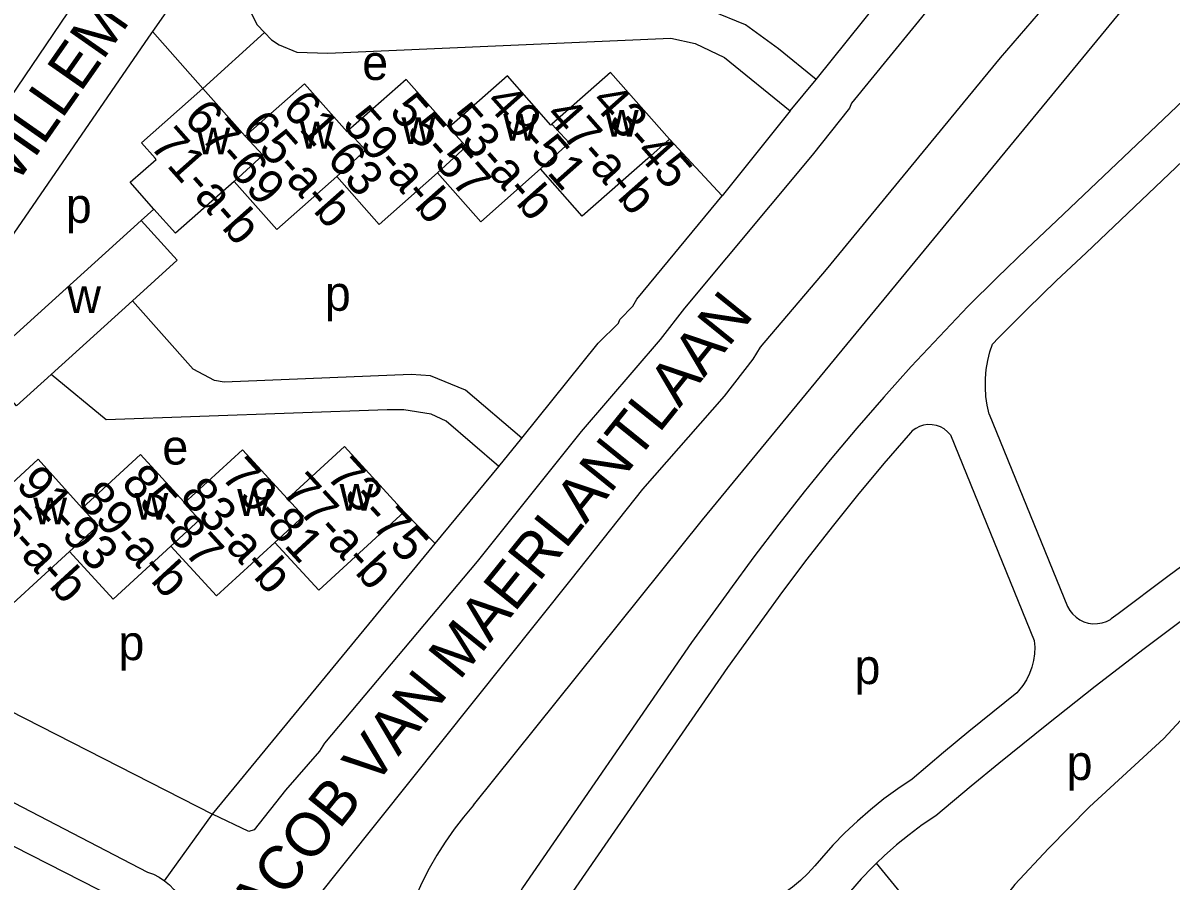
# Model space of a CAD drawing. Extents: x 159700 to 161346, y 381730 to 382922.
# Drawn here: x 160840.3 to 160971.8, y 381917.2 to 382015.5 of the extents above; entities that cross this region are included whole.
import ezdxf

# ---------------------------------------------------------------- set-up
doc = ezdxf.new("R2010")
doc.units = 0
for name, color, linetype in [('BLT_Basislijn', 7, 'Continuous'), ('BLT_Bebouwing', 7, 'Continuous'), ('BLT_Centroide', 7, 'Continuous'), ('BLT_Huisnummer_reeks', 7, 'Continuous'), ('BLT_Onderverdeling_panden', 7, 'Continuous'), ('BLT_Straatnaam', 7, 'Continuous'), ('BLT_Vlakafsluiter', 7, 'Continuous')]:
    doc.layers.add(name, color=color, linetype=linetype)

msp = doc.modelspace()

# ---------------------------------------------------------------- linework, layer by layer
at = {"layer": 'BLT_Basislijn'}
for p, q in [((160958.66, 381992.87), (160992.04, 382024.66)), ((160918.1, 381958.62), (160970.62, 382022.44)), ((160855.12, 382014.54), (160860.87, 382007.99)), ((160867.92, 382014.43), (160860.87, 382007.99)), ((160928.14, 382005.45), (160931.13, 382009.02)), ((160928.14, 382005.45), (160920.36, 381995.73)), ((160962.05, 381989.2), (160978.76, 382005.11)), ((160920.36, 381995.73), (160914.31, 382002.2)), ((160705.83, 381995.32), (160854.54, 381918.26)), ((160853.8, 381992.9), (160855.27, 381994.19)), ((160950.93, 381970.71), (160959.9, 381948.7)), ((160894.76, 381964.73), (160897.42, 381967.95)), ((160946.49, 381968.34), (160956.09, 381944.8)), ((160887.46, 381955.88), (160894.76, 381964.73)), ((160887.46, 381955.88), (160883.94, 381959.54)), ((160891.86, 381925.93), (160918.1, 381958.62)), ((160921.1, 381950.42), (160916.85, 381944.54)), ((160925.16, 381947.5), (160920.96, 381941.7)), ((160945.68, 381931.96), (160942.1, 381928.92)), ((160948.87, 381928.11), (160944.81, 381924.72)), ((160854.63, 381913.36), (160834.95, 381923.34))]:
    msp.add_line(p, q, dxfattribs=at)
for points in [[(160869.82, 381910.13), (160903.05, 381951.79), (160911.26, 381962.12), (160920.61, 381972.78), (160923.88, 381976.99), (160924.72, 381978.39), (160932.29, 381987.27), (160952.21, 382011.52), (160956.58, 382016.57), (160959.68, 382020.5), (160961.97, 382022.98), (160980.7, 382045.61), (160986.69, 382052.53), (161016.71, 382083.47)], [(160883.99, 382072.81), (160870.54, 382052.66), (160865.04, 382045.05), (160858.65, 382035.7), (160858.47, 382035.66), (160858.03, 382034.8), (160853.13, 382028.14), (160852.91, 382027.61), (160852.73, 382027.57), (160828.11, 381991.25), (160827.9, 381991.18), (160827.79, 381990.75), (160827.27, 381990.23), (160823.65, 381984.68), (160823.44, 381984.61), (160821.73, 381981.82), (160817.59, 381976.14), (160816.77, 381975.28), (160804.69, 381957.09), (160803.57, 381956.03), (160800.6, 381955.73), (160797.89, 381956.96), (160781.74, 381965.52)], [(160884, 382056.53), (160883.61, 382055.97), (160866.64, 382031.03), (160855.12, 382014.54)], [(160931.13, 382009.02), (160947.17, 382029.06), (160956.82, 382040.05), (160957.75, 382041.22), (160958.14, 382041.7)], [(160931.13, 382009.02), (160926.81, 382012.53), (160923, 382015.29), (160919.1, 382016.89), (160916.05, 382017.84), (160909.67, 382018.24), (160883.9, 382017.28), (160882.67, 382017.87), (160881.77, 382018.95), (160880.98, 382021.61), (160879.95, 382023.99), (160878.1, 382026.03), (160875.48, 382027.17), (160874.43, 382027.33), (160871.72, 382027.17), (160869.11, 382026.16), (160867.36, 382024.66), (160866.35, 382022.4), (160865.9, 382020.6), (160866.09, 382017.23), (160867.1, 382015.29), (160867.92, 382014.43)], [(160946.57, 382020.33), (160935.16, 382006.34), (160934.94, 382005.76), (160930.65, 382000.36), (160916.04, 381982.84), (160913.24, 381979.24), (160904.18, 381968.73), (160892.29, 381953.83), (160874.79, 381933.03), (160874.24, 381932.11), (160870.34, 381927.64), (160866.74, 381923.09), (160866.14, 381922.9), (160861.98, 381924.9)], [(160855.12, 382014.54), (160854.65, 382013.88), (160825.11, 381970.95)], [(160867.92, 382014.43), (160868.74, 382013.58), (160869.6, 382013), (160871.62, 382012.18), (160875.2, 382012.05), (160914.45, 382013.77), (160917.26, 382013.14), (160920.6, 382011.55), (160928.14, 382005.45)], [(160897.42, 381967.95), (160906.16, 381978.82), (160908.48, 381981.13), (160908.64, 381981.55), (160910.1, 381983.08), (160910.58, 381983.88), (160919.81, 381995.05), (160920.36, 381995.73)], [(160958.66, 381992.87), (160955.22, 381989.65), (160951.83, 381986.36), (160948.5, 381983.02), (160945.23, 381979.62), (160942.01, 381976.17), (160938.85, 381972.67), (160935.75, 381969.11), (160932.72, 381965.49), (160929.74, 381961.83), (160926.83, 381958.12), (160923.98, 381954.36), (160921.2, 381950.55), (160921.1, 381950.42)], [(160962.05, 381989.2), (160958.64, 381986), (160955.28, 381982.74), (160951.98, 381979.43), (160951.31, 381978.74)], [(160897.42, 381967.95), (160890.95, 381973.45), (160886.96, 381975.1), (160884.73, 381975.26), (160863.33, 381974.39), (160862.22, 381974.55), (160859.76, 381975.87), (160852.81, 381983.68)], [(160950.93, 381970.71), (160950.7, 381971.72), (160950.55, 381972.74), (160950.49, 381973.77), (160950.5, 381974.8), (160950.59, 381975.83), (160950.76, 381976.85), (160951.01, 381977.85), (160951.31, 381978.74)], [(160894.76, 381964.73), (160888.72, 381969.91), (160887.03, 381970.72), (160883.9, 381971.2), (160881.99, 381971.2), (160849.78, 381970.05), (160843.48, 381975.24)], [(160825.11, 381970.95), (160824.58, 381970.18), (160819.71, 381963.29), (160813.49, 381953.61), (160813.55, 381950.74), (160814.22, 381949.34), (160815.59, 381948.27), (160831.52, 381940.43), (160861.98, 381924.9)], [(160946.49, 381968.34), (160946.16, 381968.7), (160945.78, 381969.01), (160945.35, 381969.25), (160944.89, 381969.41), (160944.4, 381969.5), (160943.91, 381969.51), (160943.42, 381969.44), (160942.96, 381969.29), (160942.52, 381969.07), (160942.12, 381968.78), (160941.91, 381968.58)], [(160941.91, 381968.58), (160938.86, 381965.04), (160935.86, 381961.45), (160932.93, 381957.81), (160930.06, 381954.12), (160927.25, 381950.38), (160925.16, 381947.5)], [(160995.43, 381962.27), (160995.93, 381961.46), (160996.3, 381955.55), (160992, 381949.83), (160984.88, 381945.71), (160979.52, 381942.06), (160974.74, 381937.67), (160970.93, 381933.55), (160962.4, 381925.74), (160957.73, 381920.97), (160953.86, 381916.83), (160951.54, 381913.88), (160946.96, 381911.83), (160943.32, 381912.8), (160938.04, 381919.3)], [(160982.85, 381960.46), (160977.09, 381956.33), (160971.37, 381952.12), (160965.7, 381947.86), (160964.91, 381947.25)], [(160985.74, 381956.38), (160980, 381952.26), (160974.31, 381948.08), (160968.67, 381943.83), (160963.07, 381939.52), (160957.52, 381935.14), (160952.02, 381930.7), (160948.87, 381928.11)], [(160861.98, 381924.9), (160886.8, 381955.07), (160887.46, 381955.88)], [(160959.9, 381948.7), (160960.16, 381948.24), (160960.48, 381947.83), (160960.87, 381947.47), (160961.3, 381947.17), (160961.78, 381946.94), (160962.28, 381946.79), (160962.8, 381946.71), (160963.33, 381946.72), (160963.85, 381946.8), (160964.35, 381946.96), (160964.82, 381947.2), (160964.91, 381947.25)], [(160916.85, 381944.54), (160897.46, 381916.45), (160890.84, 381904.2)], [(160956.09, 381944.8), (160956.14, 381944.02), (160956.1, 381943.25), (160955.99, 381942.48), (160955.8, 381941.73), (160955.53, 381941), (160955.19, 381940.3), (160954.78, 381939.64), (160954.3, 381939.03), (160954.1, 381938.81)], [(160920.96, 381941.7), (160901.73, 381913.83), (160897.63, 381906.26)], [(160954.1, 381938.81), (160948.59, 381934.35), (160945.68, 381931.96)], [(160942.1, 381928.92), (160940.46, 381927.81), (160938.87, 381926.64), (160937.33, 381925.4), (160935.84, 381924.1), (160934.41, 381922.75), (160933.03, 381921.34), (160931.71, 381919.87), (160930.97, 381918.99)], [(160891.86, 381925.93), (160890.72, 381924.57), (160889.64, 381923.17), (160888.63, 381921.71), (160887.68, 381920.22), (160886.8, 381918.68), (160885.99, 381917.1), (160885.25, 381915.49), (160884.81, 381914.42)], [(160944.81, 381924.72), (160943.27, 381923.67), (160941.77, 381922.55), (160940.31, 381921.38), (160938.91, 381920.14), (160938.04, 381919.3)], [(160938.04, 381919.3), (160937.57, 381918.84), (160936.28, 381917.48), (160935.05, 381916.07), (160933.88, 381914.61), (160932.77, 381913.11), (160932.25, 381912.34)], [(160854.54, 381918.26), (160855.23, 381918.01), (160855.88, 381917.68), (160856.49, 381917.28), (160857.05, 381916.82), (160857.56, 381916.29), (160858.01, 381915.72), (160858.4, 381915.1), (160858.71, 381914.44), (160858.95, 381913.75), (160859.11, 381913.04), (160859.2, 381912.32), (160859.2, 381911.59), (160859.13, 381910.86), (160858.97, 381910.15), (160858.74, 381909.46), (160858.59, 381909.1)], [(160930.97, 381918.99), (160930.16, 381918.11), (160929.3, 381917.3), (160928.39, 381916.54), (160927.43, 381915.85), (160926.96, 381915.54)]]:
    msp.add_lwpolyline(points, dxfattribs=at)
at = {"layer": 'BLT_Bebouwing'}
for p, q in [((160865.73, 382002.55), (160860.87, 382007.99)), ((160852.81, 381983.68), (160843.48, 381975.24))]:
    msp.add_line(p, q, dxfattribs=at)
for points in [[(160889.05, 382003.52), (160884.15, 382009.05), (160877.47, 382003.14)], [(160900.85, 382003.93), (160900.73, 382003.82), (160895.76, 382009.45), (160889.05, 382003.52)], [(160914.31, 382002.2), (160907.55, 382009.85), (160900.85, 382003.93)], [(160855.27, 381994.19), (160852.55, 381997.27), (160855.51, 381999.89), (160855.4, 382000.01), (160853.84, 382001.78), (160860.87, 382007.99)], [(160877.47, 382003.14), (160877.38, 382003.05), (160872.51, 382008.55), (160865.73, 382002.55)], [(160914.31, 382002.2), (160911.82, 382000), (160904.33, 381993.37), (160899.54, 381998.79)], [(160887.76, 381998.35), (160881.08, 381992.44), (160876.21, 381997.94)], [(160899.54, 381998.79), (160892.72, 381992.75), (160887.76, 381998.35)], [(160864.45, 381997.37), (160857.73, 381991.42), (160855.27, 381994.19)], [(160876.21, 381997.94), (160869.33, 381991.86), (160864.45, 381997.37)], [(160838.52, 381972.8), (160835.41, 381976.24), (160853.8, 381992.9)], [(160853.8, 381992.9), (160857.94, 381988.33), (160852.81, 381983.68)], [(160843.48, 381975.24), (160839.54, 381971.67), (160838.52, 381972.8)], [(160870.56, 381961.03), (160865.42, 381966.63), (160858.74, 381960.5)], [(160883.94, 381959.54), (160877.08, 381967.02), (160870.56, 381961.03)], [(160847.05, 381959.96), (160842.02, 381965.55), (160835.48, 381959.57)], [(160858.74, 381960.5), (160858.71, 381960.68), (160853.74, 381966.1), (160847.05, 381959.96)], [(160869.13, 381956.02), (160874.15, 381950.55), (160883.94, 381959.54)], [(160834.05, 381954.55), (160839.12, 381949.02), (160845.6, 381954.97)], [(160845.6, 381954.97), (160850.6, 381949.53), (160857.21, 381955.6)], [(160857.21, 381955.6), (160862.45, 381949.89), (160869.13, 381956.02)]]:
    msp.add_lwpolyline(points, dxfattribs=at)
at = {"layer": 'BLT_Onderverdeling_panden'}
for points in [[(160887.76, 381998.35), (160891.04, 382001.36), (160889.05, 382003.52)], [(160899.54, 381998.79), (160902.81, 382001.79), (160900.85, 382003.93)], [(160864.45, 381997.37), (160867.73, 382000.37), (160865.73, 382002.55)], [(160876.21, 381997.94), (160879.48, 382000.94), (160877.47, 382003.14)], [(160857.21, 381955.6), (160860.48, 381958.6), (160858.74, 381960.5)], [(160869.13, 381956.02), (160872.4, 381959.02), (160870.56, 381961.03)], [(160845.6, 381954.97), (160848.87, 381957.97), (160847.05, 381959.96)]]:
    msp.add_lwpolyline(points, dxfattribs=at)
at = {"layer": 'BLT_Vlakafsluiter'}
msp.add_line((160856.49, 381917.28), (160861.98, 381924.9), dxfattribs=at)

# ---------------------------------------------------------------- texts
at = {"layer": 'BLT_Centroide'}
for s, p in [('e', (160879.12, 382008.98)), ('w', (160883.62, 382001.64)), ('w', (160895.28, 382002.03)), ('w', (160906.92, 382002.48)), ('w', (160860.14, 382000.45)), ('w', (160871.97, 382001.12)), ('p', (160845.17, 381992.62)), ('w', (160845.34, 381982.28)), ('p', (160874.84, 381982.55)), ('e', (160856.23, 381964.94)), ('w', (160876.53, 381959.64)), ('w', (160853.05, 381958.62)), ('w', (160864.81, 381959.05)), ('w', (160841.45, 381958.09)), ('p', (160851.2, 381942.54)), ('p', (160935.5, 381939.8)), ('p', (160959.79, 381928.81))]:
    msp.add_text(s, height=4, dxfattribs=at).set_placement(p)
at = {"layer": 'BLT_Huisnummer_reeks'}
for s, rotation, p in [('61-63', 311.5095, (160869.81, 382005.59)), ('55-57', 311.5028, (160882.1, 382005.28)), ('49-51', 311.5024, (160893.1, 382006.35)), ('43-45', 311.5019, (160905.2, 382006.45)), ('67-69', 311.5095, (160858.54, 382004.55)), ('59-a-b', 311.5028, (160876.72, 382003.82)), ('53-a-b', 311.5024, (160888.35, 382004.18)), ('47-a-b', 311.5019, (160899.95, 382004.83)), ('65-a-b', 311.5095, (160865.15, 382003.31)), ('71-a-b', 311.5095, (160854.66, 382001.39)), ('79-81', 312.5586, (160862.82, 381963.5)), ('73-75', 312.5531, (160874.87, 381963.55)), ('91-93', 312.5527, (160839.32, 381962.54)), ('85-87', 312.5547, (160851.38, 381962.71)), ('77-a-b', 312.5531, (160869.75, 381961.73)), ('89-a-b', 312.5547, (160846.35, 381960.79)), ('83-a-b', 312.5586, (160858.12, 381961.23)), ('95-a-b', 312.5527, (160834.7, 381960.17))]:
    msp.add_text(s, height=4, rotation=rotation, dxfattribs=at).set_placement(p)
at = {"layer": 'BLT_Straatnaam'}
for s, height, rotation, p in [('WILLEM KLOOSLAAN', 5, 55.0394, (160837.92, 381994.69)), ('JACOB VAN MAERLANTLAAN', 4.9999, 51.0994, (160865.29, 381909.18))]:
    msp.add_text(s, height=height, rotation=rotation, dxfattribs=at).set_placement(p)

doc.saveas('drawing.dxf')
